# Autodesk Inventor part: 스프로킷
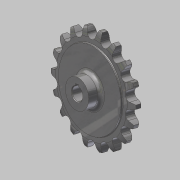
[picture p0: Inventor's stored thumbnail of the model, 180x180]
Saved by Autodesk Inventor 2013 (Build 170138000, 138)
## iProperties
Created: 2016-03
Part Number: 스프로킷
Material: 강철, 탄소
Document SubType Name: Modeling
Designer: mduedu
Density: 7.87 g/cm^3
Mass: 301.87 g
Surface Area: 120.622 cm^2
Volume: 38.3571 cm^3
Author: mduedu
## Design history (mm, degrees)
sketch "스케치1"
  geometry: L1 (0, 5)-(29.5, 5); L2 (29.5, 5)-(29.5, 4.1); L3 (30, 3.6)-(33.625, 3.6); L4 (40, 2)-(40, 0); L5 (40, 0)-(0, 0); L6 (0, 0)-(0, 5); L7 (0, -5)-(29.5, -5); L8 (29.5, -5)-(29.5, -4.1); L9 (30, -3.6)-(33.625, -3.6); L10 (40, -2)-(40, 0); L11 (0, 0)-(0, -5); A1 r 13.5 centre (33.625, -9.9) between (40, 2) and (33.625, 3.6); A2 r 13.5 centre (33.625, 9.9) between (33.625, -3.6) and (40, -2); A3 r 0.5 centre (30, 4.1) between (29.5, 4.1) and (30, 3.6); A4 r 0.5 centre (30, -4.1) between (30, -3.6) and (29.5, -4.1); 2 further points
  constraints: 22 end point, 8 point on circle, 6 symmetric about line, 5 tangent, 4 centre point, 4 parallel, 4 point on line, 1 equal radius, 1 horizontal, 1 perpendicular, 1 other
  dimensions: "d0" = 80 diameter of L4 L6; "d2" = 59 diameter of L2 L6; "d3" = 1.6 vertical distance of L4.start L3.end; "d4" = 3.6 distance from line of L4.end L3; "d5" = 5 distance between parallel lines of L5 L1; "d6" = 13.5 radius of A1; "d15" = 0.5 radius of A3
revolve "회전1" sketch "스케치1" stored, may be unused: angle "d7" = 90 deg
sketch "스케치2" dims "d8" = 65.2, "d11" = 80
  geometry: L1 (0, 0)-(0, 32.6); A1 r 36.57 centre (0, 0) between (-16.231, 32.771) and (0, 36.57); A2 r 3.97 centre (0, 36.57) between (-3.866, 35.665) and (0, 32.6); A3 r 12.7 centre (-16.231, 32.771) between (-3.866, 35.665) and (-5.534, 39.615); A4 r 12.7 centre (16.231, 32.771) between (5.534, 39.615) and (3.866, 35.665); A5 r 3.97 centre (0, 36.57) between (0, 32.6) and (3.866, 35.665); A6 r 40 centre (0, 0) between (5.534, 39.615) and (-5.534, 39.615); 2 further points
  constraints: 12 point on circle, 6 centre point, 4 coincident, 3 symmetric about line, 2 end point, 1 point on line, 1 tangent, 1 vertical, 1 vertical alignment, 7 other
  dimensions: "d10" = 73.14 diameter of A1; "d12" = 12.7 radius of A3
extrude "돌출1" cut sketch "스케치2" stored distance "d13" = 10; taper "d14" = 0 deg
sketch "스케치3"
  geometry: C1 r 11 at (0, 0); 1 further point
  constraints: 1 centre point, 1 coincident
  dimensions: "d19" = 22 diameter of C1
extrude "돌출2" join sketch "스케치3" distance "d20" = 10; taper "d21" = 0 deg
fillet "모깎기1" dims "d22" = 3
sketch "스케치4"
  geometry: L1 (-1.5, 0)-(1.5, 0); L2 (1.5, 0)-(1.5, 6.4); L3 (1.5, 6.4)-(-1.5, 6.4); L4 (-1.5, 6.4)-(-1.5, 0); C1 r 5 at (0, 0); 2 further points
  constraints: 8 end point, 2 coincident, 2 parallel, 1 centre point, 1 horizontal, 1 midpoint, 1 perpendicular
  dimensions: "d23" = 10 diameter of C1; "d25" = 3 distance of L2.end L3.end; "d26" = 6.4 distance of L1.end L2.end
extrude "돌출3" cut sketch "스케치4" stored distance "d27" = 8; taper "d28" = 0 deg
chamfer "모따기1" distance "d29" = 0.5; stored, may be unused: second distance "d30" = 2, angle "d31" = 45 deg
sketch "스케치5" dims "d33" = 50
  geometry: C1 r 1 at (0, 25); 2 further points
  constraints: 2 vertical alignment, 1 centre point, 1 coincident, 2 other
  dimensions: "d32" = 2 diameter of C1
extrude "돌출4" join sketch "스케치5" distance "d34" = 0.5; taper "d35" = 0 deg
node "솔리드1"
pattern_circular "원형 패턴1" dims angle "d17" = 360 deg
